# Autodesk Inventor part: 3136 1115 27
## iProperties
Shininess: 20.0
Length Units: 11269
Angle Units: 11279
Time Units: 11290
Mass Units: 11283
Length Display Precision: 3
Angle Display Precision: 2
Compacted: True
Created: 2000-11
Part Number: 3136 1115 27
Material: Steel, Mild
Document SubType Name: Modeling
Designer: Joe M
Engineer: Joe M
Density: 0.0
Volumn: 0.0
Area: 0.0
PropertySet Name: Model Information
Control State: 0
Master: False
Checked Out: False
Last Check In By: brpog
Last Check In Date: 2001-02-28
Author: Joe M
